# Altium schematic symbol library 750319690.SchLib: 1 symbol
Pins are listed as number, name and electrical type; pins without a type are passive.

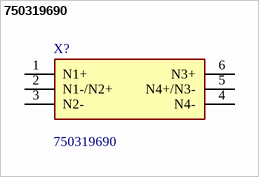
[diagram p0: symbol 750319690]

## 750319690
designator X?
WE-PPTI Push-Pull Transformer TOR6/3/3 SMT; Ui = 12V; Uo1 = 5V/0.7A; f = 400-600kHz; Manufacturer_Name: Wurth Elektronik; Geometry.Height: 5.5mm
footprint 750319690
pins: 1 N1+, 2 N1-/N2+, 3 N2-, 4 N4-, 5 N4+/N3-, 6 N3+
